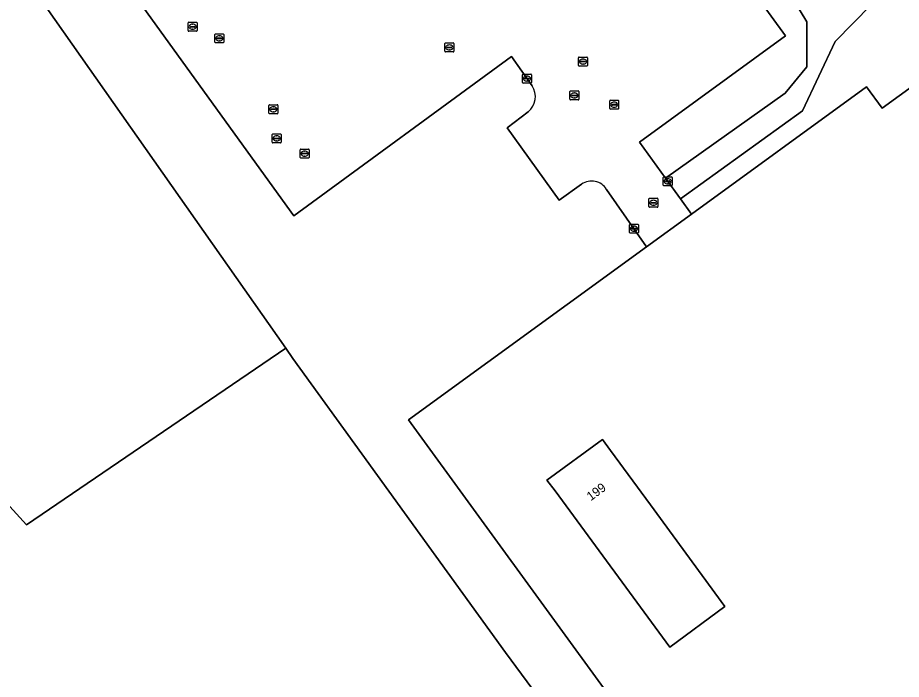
# Model space of a CAD drawing. Extents: x 160203 to 161530, y 379528 to 381797.
# Drawn here: x 160563.5 to 160662.1, y 380137.4 to 380211.2 of the extents above; entities that cross this region are included whole.
import ezdxf

# ---------------------------------------------------------------- set-up
doc = ezdxf.new("R2010")
doc.units = 0
for name, color, linetype in [('IMGEO_Erf', 7, 'Continuous'), ('IMGEO_Grasland_overig', 7, 'Continuous'), ('IMGEO_Kolk', 7, 'Continuous'), ('IMGEO_Loofbos', 7, 'Continuous'), ('IMGEO_Pand', 7, 'Continuous'), ('IMGEO_Pand_nummerreeks', 7, 'Continuous'), ('IMGEO_Parkeervlak_gesloten', 7, 'Continuous'), ('IMGEO_Rioolput', 7, 'Continuous')]:
    doc.layers.add(name, color=color, linetype=linetype)

msp = doc.modelspace()

# ---------------------------------------------------------------- linework, layer by layer
at = {"layer": 'IMGEO_Erf'}
msp.add_lwpolyline([(160832.631, 380116.995), (160854.553, 380138.278), (160818.942, 380187.917), (160814.332, 380194.343), (160832.094, 380207.451), (160830.749, 380209.298), (160801.949, 380188.395), (160801.085, 380189.491), (160829.917, 380210.442), (160817.382, 380227.667), (160800.862, 380223.411), (160795.149, 380250), (160792.697, 380261.409), (160775.626, 380285.117), (160727.25, 380250), (160659.957, 380201.152), (160658.198, 380203.535), (160638.688, 380189.336), (160633.687, 380185.696), (160607.134, 380166.371), (160661.164, 380092.122)], dxfattribs=at)
msp.add_lwpolyline([(160642.426, 380145.565), (160636.258, 380141.042), (160623.467, 380158.449), (160622.573, 380159.665), (160628.767, 380164.187), (160629.66, 380162.97), (160634.108, 380156.906)], close=True, dxfattribs=at)
at = {"layer": 'IMGEO_Grasland_overig'}
for points in [[(160627.796, 380250), (160651.549, 380210.79), (160651.567, 380205.762), (160649.135, 380202.83), (160635.795, 380193.341), (160637.459, 380191.037), (160651.065, 380200.863), (160654.734, 380208.575), (160662.709, 380216.783)], [(160659.204, 380084.561), (160617.929, 380140.449), (160601.914, 380162.597), (160594.235, 380173.217), (160593.422, 380174.377), (160564.504, 380154.675), (160513.808, 380210.429), (160507.442, 380204.215), (160500, 380194.582), (160496.442, 380189.663), (160493.08, 380184.147), (160491.345, 380180.944), (160490.502, 380178.181), (160491.03, 380175.473), (160489.767, 380174.541), (160492.953, 380170.485), (160494.114, 380171.456), (160500, 380164.601), (160528.977, 380132.135)]]:
    msp.add_lwpolyline(points, dxfattribs=at)
msp.add_lwpolyline([(160593.422, 380174.377), (160565.038, 380214.842), (160569.386, 380217.98), (160549.683, 380245.449), (160542.254, 380238.197), (160513.808, 380210.429), (160564.504, 380154.675)], close=True, dxfattribs=at)
at = {"layer": 'IMGEO_Kolk'}
for p, q in [((160585.524, 380208.514), (160585.524, 380209.366)), ((160585.599, 380209.44), (160586.451, 380209.44)), ((160585.783, 380208.934), (160585.783, 380208.946)), ((160586.221, 380208.897), (160585.823, 380208.897)), ((160585.826, 380208.983), (160586.224, 380208.983)), ((160586.035, 380208.66), (160586.01, 380208.66)), ((160586.012, 380209.22), (160586.037, 380209.22)), ((160586.267, 380208.946), (160586.267, 380208.934)), ((160586.525, 380209.366), (160586.525, 380208.514)), ((160586.451, 380208.44), (160585.599, 380208.44)), ((160611.191, 380207.496), (160611.191, 380208.348)), ((160611.266, 380208.422), (160612.118, 380208.422)), ((160611.45, 380207.916), (160611.45, 380207.928)), ((160611.888, 380207.879), (160611.49, 380207.879)), ((160611.493, 380207.965), (160611.891, 380207.965)), ((160611.702, 380207.642), (160611.677, 380207.642)), ((160611.679, 380208.202), (160611.704, 380208.202)), ((160611.934, 380207.928), (160611.934, 380207.916)), ((160612.192, 380208.348), (160612.192, 380207.496)), ((160612.118, 380207.422), (160611.266, 380207.422)), ((160626.082, 380205.924), (160626.082, 380206.776)), ((160626.157, 380206.85), (160627.009, 380206.85)), ((160626.57, 380206.63), (160626.595, 380206.63)), ((160627.083, 380206.776), (160627.083, 380205.924)), ((160627.009, 380205.85), (160626.157, 380205.85)), ((160626.341, 380206.344), (160626.341, 380206.356)), ((160626.779, 380206.307), (160626.381, 380206.307)), ((160626.384, 380206.393), (160626.782, 380206.393)), ((160626.593, 380206.07), (160626.568, 380206.07)), ((160626.825, 380206.356), (160626.825, 380206.344)), ((160619.834, 380204.027), (160619.834, 380204.879)), ((160619.909, 380204.953), (160620.761, 380204.953)), ((160620.322, 380204.733), (160620.347, 380204.733)), ((160620.835, 380204.879), (160620.835, 380204.027)), ((160620.761, 380203.953), (160619.909, 380203.953)), ((160620.093, 380204.447), (160620.093, 380204.459)), ((160620.531, 380204.41), (160620.133, 380204.41)), ((160620.136, 380204.496), (160620.534, 380204.496)), ((160620.345, 380204.173), (160620.32, 380204.173)), ((160620.577, 380204.459), (160620.577, 380204.447)), ((160629.567, 380201.119), (160629.567, 380201.971)), ((160629.642, 380202.045), (160630.494, 380202.045)), ((160630.055, 380201.825), (160630.08, 380201.825)), ((160630.568, 380201.971), (160630.568, 380201.119)), ((160591.552, 380200.604), (160591.552, 380201.456)), ((160591.627, 380201.53), (160592.479, 380201.53)), ((160591.811, 380201.024), (160591.811, 380201.036)), ((160592.249, 380200.987), (160591.851, 380200.987)), ((160591.854, 380201.073), (160592.252, 380201.073)), ((160592.063, 380200.75), (160592.038, 380200.75)), ((160592.04, 380201.31), (160592.065, 380201.31)), ((160592.295, 380201.036), (160592.295, 380201.024)), ((160592.553, 380201.456), (160592.553, 380200.604)), ((160630.494, 380201.045), (160629.642, 380201.045)), ((160629.826, 380201.539), (160629.826, 380201.551)), ((160630.264, 380201.502), (160629.866, 380201.502)), ((160629.869, 380201.588), (160630.267, 380201.588)), ((160630.078, 380201.265), (160630.053, 380201.265)), ((160630.31, 380201.551), (160630.31, 380201.539)), ((160592.479, 380200.53), (160591.627, 380200.53)), ((160595.037, 380195.659), (160595.037, 380196.511)), ((160595.112, 380196.585), (160595.964, 380196.585)), ((160595.296, 380196.079), (160595.296, 380196.091)), ((160595.734, 380196.042), (160595.336, 380196.042)), ((160595.339, 380196.128), (160595.737, 380196.128)), ((160595.548, 380195.805), (160595.523, 380195.805)), ((160595.525, 380196.365), (160595.55, 380196.365)), ((160595.78, 380196.091), (160595.78, 380196.079)), ((160596.038, 380196.511), (160596.038, 380195.659)), ((160595.964, 380195.585), (160595.112, 380195.585)), ((160635.546, 380192.569), (160635.546, 380193.421)), ((160635.621, 380193.495), (160636.473, 380193.495)), ((160635.805, 380192.989), (160635.805, 380193.001)), ((160636.243, 380192.952), (160635.845, 380192.952)), ((160635.848, 380193.038), (160636.246, 380193.038)), ((160636.034, 380193.275), (160636.059, 380193.275)), ((160636.289, 380193.001), (160636.289, 380192.989)), ((160636.547, 380193.421), (160636.547, 380192.569)), ((160636.473, 380192.495), (160635.621, 380192.495)), ((160636.057, 380192.715), (160636.032, 380192.715)), ((160631.775, 380187.288), (160631.775, 380188.14)), ((160631.85, 380188.214), (160632.702, 380188.214)), ((160632.263, 380187.994), (160632.288, 380187.994)), ((160632.776, 380188.14), (160632.776, 380187.288)), ((160632.702, 380187.214), (160631.85, 380187.214)), ((160632.034, 380187.708), (160632.034, 380187.72)), ((160632.472, 380187.671), (160632.074, 380187.671)), ((160632.077, 380187.757), (160632.475, 380187.757)), ((160632.286, 380187.434), (160632.261, 380187.434)), ((160632.518, 380187.72), (160632.518, 380187.708))]:
    msp.add_line(p, q, dxfattribs=at)
for points in [[(160585.524, 380208.514), (160585.524, 380209.366)], [(160585.599, 380209.44), (160586.451, 380209.44)], [(160586.525, 380209.366), (160586.525, 380208.514)], [(160586.451, 380208.44), (160585.599, 380208.44)], [(160611.191, 380207.496), (160611.191, 380208.348)], [(160611.266, 380208.422), (160612.118, 380208.422)], [(160612.192, 380208.348), (160612.192, 380207.496)], [(160612.118, 380207.422), (160611.266, 380207.422)], [(160626.082, 380205.924), (160626.082, 380206.776)], [(160626.157, 380206.85), (160627.009, 380206.85)], [(160627.083, 380206.776), (160627.083, 380205.924)], [(160627.009, 380205.85), (160626.157, 380205.85)], [(160619.834, 380204.027), (160619.834, 380204.879)], [(160619.909, 380204.953), (160620.761, 380204.953)], [(160620.835, 380204.879), (160620.835, 380204.027)], [(160620.761, 380203.953), (160619.909, 380203.953)], [(160629.567, 380201.119), (160629.567, 380201.971)], [(160629.642, 380202.045), (160630.494, 380202.045)], [(160630.568, 380201.971), (160630.568, 380201.119)], [(160591.552, 380200.604), (160591.552, 380201.456)], [(160591.627, 380201.53), (160592.479, 380201.53)], [(160592.553, 380201.456), (160592.553, 380200.604)], [(160630.494, 380201.045), (160629.642, 380201.045)], [(160592.479, 380200.53), (160591.627, 380200.53)], [(160595.037, 380195.659), (160595.037, 380196.511)], [(160595.112, 380196.585), (160595.964, 380196.585)], [(160596.038, 380196.511), (160596.038, 380195.659)], [(160595.964, 380195.585), (160595.112, 380195.585)], [(160635.546, 380192.569), (160635.546, 380193.421)], [(160635.621, 380193.495), (160636.473, 380193.495)], [(160636.547, 380193.421), (160636.547, 380192.569)], [(160636.473, 380192.495), (160635.621, 380192.495)], [(160631.775, 380187.288), (160631.775, 380188.14)], [(160631.85, 380188.214), (160632.702, 380188.214)], [(160632.776, 380188.14), (160632.776, 380187.288)], [(160632.702, 380187.214), (160631.85, 380187.214)]]:
    msp.add_lwpolyline(points, dxfattribs=at)
for centre, radius, start, end in [((160585.601, 380209.364), 0.0765, 91.55205, 178.44795), ((160585.601, 380209.364), 0.0765, 91.55205, 178.44795), ((160585.823, 380208.943), 0.0403, 85.87752, 175.75265), ((160585.82, 380208.933), 0.0366, 178.93798, 274.71019), ((160586.224, 380208.94), 0.043, 264.86636, 352.45326), ((160586.228, 380208.945), 0.0386, 1.73085, 96.63898), ((160586.449, 380209.364), 0.0765, 1.55205, 88.44795), ((160586.449, 380209.364), 0.0765, 1.55205, 88.44795), ((160585.601, 380208.516), 0.0765, 181.55205, 268.44795), ((160585.601, 380208.516), 0.0765, 181.55205, 268.44795), ((160586.449, 380208.516), 0.0765, 271.55205, 358.44795), ((160586.449, 380208.516), 0.0765, 271.55205, 358.44795), ((160611.268, 380208.346), 0.0765, 91.55205, 178.44795), ((160611.268, 380208.346), 0.0765, 91.55205, 178.44795), ((160611.49, 380207.925), 0.0403, 85.87752, 175.75265), ((160611.487, 380207.915), 0.0366, 178.93798, 274.71019), ((160611.891, 380207.922), 0.043, 264.86636, 352.45326), ((160611.895, 380207.927), 0.0386, 1.73085, 96.63898), ((160612.116, 380208.346), 0.0765, 1.55205, 88.44795), ((160612.116, 380208.346), 0.0765, 1.55205, 88.44795), ((160611.268, 380207.498), 0.0765, 181.55205, 268.44795), ((160611.268, 380207.498), 0.0765, 181.55205, 268.44795), ((160612.116, 380207.498), 0.0765, 271.55205, 358.44795), ((160612.116, 380207.498), 0.0765, 271.55205, 358.44795), ((160626.159, 380206.774), 0.0765, 91.55205, 178.44795), ((160626.159, 380206.774), 0.0765, 91.55205, 178.44795), ((160627.007, 380206.774), 0.0765, 1.55205, 88.44795), ((160627.007, 380206.774), 0.0765, 1.55205, 88.44795), ((160626.159, 380205.926), 0.0765, 181.55205, 268.44795), ((160626.159, 380205.926), 0.0765, 181.55205, 268.44795), ((160626.381, 380206.353), 0.0403, 85.87752, 175.75265), ((160626.378, 380206.343), 0.0366, 178.93798, 274.71019), ((160626.782, 380206.35), 0.043, 264.86636, 352.45326), ((160626.786, 380206.355), 0.0386, 1.73085, 96.63898), ((160627.007, 380205.926), 0.0765, 271.55205, 358.44795), ((160627.007, 380205.926), 0.0765, 271.55205, 358.44795), ((160619.911, 380204.877), 0.0765, 91.55205, 178.44795), ((160619.911, 380204.877), 0.0765, 91.55205, 178.44795), ((160620.759, 380204.877), 0.0765, 1.55205, 88.44795), ((160620.759, 380204.877), 0.0765, 1.55205, 88.44795), ((160619.911, 380204.029), 0.0765, 181.55205, 268.44795), ((160619.911, 380204.029), 0.0765, 181.55205, 268.44795), ((160620.133, 380204.456), 0.0403, 85.87752, 175.75265), ((160620.13, 380204.446), 0.0366, 178.93798, 274.71019), ((160620.534, 380204.453), 0.043, 264.86636, 352.45326), ((160620.538, 380204.458), 0.0386, 1.73085, 96.63898), ((160620.759, 380204.029), 0.0765, 271.55205, 358.44795), ((160620.759, 380204.029), 0.0765, 271.55205, 358.44795), ((160629.644, 380201.969), 0.0765, 91.55205, 178.44795), ((160629.644, 380201.969), 0.0765, 91.55205, 178.44795), ((160630.492, 380201.969), 0.0765, 1.55205, 88.44795), ((160630.492, 380201.969), 0.0765, 1.55205, 88.44795), ((160591.629, 380201.454), 0.0765, 91.55205, 178.44795), ((160591.629, 380201.454), 0.0765, 91.55205, 178.44795), ((160591.851, 380201.033), 0.0403, 85.87752, 175.75265), ((160591.848, 380201.023), 0.0366, 178.93798, 274.71019), ((160592.252, 380201.03), 0.043, 264.86636, 352.45326), ((160592.256, 380201.035), 0.0386, 1.73085, 96.63898), ((160592.477, 380201.454), 0.0765, 1.55205, 88.44795), ((160592.477, 380201.454), 0.0765, 1.55205, 88.44795), ((160629.644, 380201.121), 0.0765, 181.55205, 268.44795), ((160629.644, 380201.121), 0.0765, 181.55205, 268.44795), ((160629.866, 380201.548), 0.0403, 85.87752, 175.75265), ((160629.863, 380201.538), 0.0366, 178.93798, 274.71019), ((160630.267, 380201.545), 0.043, 264.86636, 352.45326), ((160630.271, 380201.55), 0.0386, 1.73085, 96.63898), ((160630.492, 380201.121), 0.0765, 271.55205, 358.44795), ((160630.492, 380201.121), 0.0765, 271.55205, 358.44795), ((160591.629, 380200.606), 0.0765, 181.55205, 268.44795), ((160591.629, 380200.606), 0.0765, 181.55205, 268.44795), ((160592.477, 380200.606), 0.0765, 271.55205, 358.44795), ((160592.477, 380200.606), 0.0765, 271.55205, 358.44795), ((160595.114, 380196.509), 0.0765, 91.55205, 178.44795), ((160595.114, 380196.509), 0.0765, 91.55205, 178.44795), ((160595.336, 380196.088), 0.0403, 85.87752, 175.75265), ((160595.333, 380196.078), 0.0366, 178.93798, 274.71019), ((160595.737, 380196.085), 0.043, 264.86636, 352.45326), ((160595.741, 380196.09), 0.0386, 1.73085, 96.63898), ((160595.962, 380196.509), 0.0765, 1.55205, 88.44795), ((160595.962, 380196.509), 0.0765, 1.55205, 88.44795), ((160595.114, 380195.661), 0.0765, 181.55205, 268.44795), ((160595.114, 380195.661), 0.0765, 181.55205, 268.44795), ((160595.962, 380195.661), 0.0765, 271.55205, 358.44795), ((160595.962, 380195.661), 0.0765, 271.55205, 358.44795), ((160635.623, 380193.419), 0.0765, 91.55205, 178.44795), ((160635.623, 380193.419), 0.0765, 91.55205, 178.44795), ((160635.845, 380192.998), 0.0403, 85.87752, 175.75265), ((160635.842, 380192.988), 0.0366, 178.93798, 274.71019), ((160636.246, 380192.995), 0.043, 264.86636, 352.45326), ((160636.25, 380193), 0.0386, 1.73085, 96.63898), ((160636.471, 380193.419), 0.0765, 1.55205, 88.44795), ((160636.471, 380193.419), 0.0765, 1.55205, 88.44795), ((160635.623, 380192.571), 0.0765, 181.55205, 268.44795), ((160635.623, 380192.571), 0.0765, 181.55205, 268.44795), ((160636.471, 380192.571), 0.0765, 271.55205, 358.44795), ((160636.471, 380192.571), 0.0765, 271.55205, 358.44795), ((160631.852, 380188.138), 0.0765, 91.55205, 178.44795), ((160631.852, 380188.138), 0.0765, 91.55205, 178.44795), ((160632.7, 380188.138), 0.0765, 1.55205, 88.44795), ((160632.7, 380188.138), 0.0765, 1.55205, 88.44795), ((160631.852, 380187.29), 0.0765, 181.55205, 268.44795), ((160631.852, 380187.29), 0.0765, 181.55205, 268.44795), ((160632.074, 380187.717), 0.0403, 85.87752, 175.75265), ((160632.071, 380187.707), 0.0366, 178.93798, 274.71019), ((160632.475, 380187.714), 0.043, 264.86636, 352.45326), ((160632.479, 380187.719), 0.0386, 1.73085, 96.63898), ((160632.7, 380187.29), 0.0765, 271.55205, 358.44795), ((160632.7, 380187.29), 0.0765, 271.55205, 358.44795)]:
    msp.add_arc(centre, radius, start, end, dxfattribs=at)
for centre, major_axis, ratio, start_param, end_param in [((160586.011, 380208.94), (-0.387, 0.002), 0.722429, 4.712389, 7.853982), ((160586.036, 380208.94), (-0.39, 0.002), 0.717154, 1.570796, 4.712389), ((160611.678, 380207.922), (-0.387, 0.002), 0.722429, 4.712389, 7.853982), ((160611.703, 380207.922), (-0.39, 0.002), 0.717154, 1.570796, 4.712389), ((160626.569, 380206.35), (-0.387, 0.002), 0.722429, 4.712389, 7.853982), ((160626.594, 380206.35), (-0.39, 0.002), 0.717154, 1.570796, 4.712389), ((160620.321, 380204.453), (-0.387, 0.002), 0.722429, 4.712389, 7.853982), ((160620.346, 380204.453), (-0.39, 0.002), 0.717154, 1.570796, 4.712389), ((160630.054, 380201.545), (-0.387, 0.002), 0.722429, 4.712389, 7.853982), ((160630.079, 380201.545), (-0.39, 0.002), 0.717154, 1.570796, 4.712389), ((160592.039, 380201.03), (-0.387, 0.002), 0.722429, 4.712389, 7.853982), ((160592.064, 380201.03), (-0.39, 0.002), 0.717154, 1.570796, 4.712389), ((160595.524, 380196.085), (-0.387, 0.002), 0.722429, 4.712389, 7.853982), ((160595.549, 380196.085), (-0.39, 0.002), 0.717154, 1.570796, 4.712389), ((160636.033, 380192.995), (-0.387, 0.002), 0.722429, 4.712389, 7.853982), ((160636.058, 380192.995), (-0.39, 0.002), 0.717154, 1.570796, 4.712389), ((160632.262, 380187.714), (-0.387, 0.002), 0.722429, 4.712389, 7.853982), ((160632.287, 380187.714), (-0.39, 0.002), 0.717154, 1.570796, 4.712389)]:
    msp.add_ellipse(centre, major_axis=major_axis, ratio=ratio, start_param=start_param, end_param=end_param, dxfattribs=at)
at = {"layer": 'IMGEO_Loofbos'}
for points in [[(160620.919, 380203.629), (160618.605, 380206.899), (160594.333, 380189.136), (160575.672, 380215.009), (160599.849, 380232.562), (160587.202, 380249.921), (160573.362, 380269.257), (160570.804, 380266.005), (160582.632, 380250), (160593.458, 380235.35), (160569.386, 380217.98), (160565.038, 380214.842), (160593.422, 380174.377), (160594.235, 380173.217), (160601.914, 380162.597), (160617.929, 380140.449), (160659.204, 380084.561)], [(160611.738, 380226.54), (160614.05, 380223.39), (160630.278, 380235.161), (160649.168, 380209.228), (160632.901, 380197.347), (160635.795, 380193.341), (160649.135, 380202.83), (160651.567, 380205.762), (160651.549, 380210.79), (160627.796, 380250)], [(160662.709, 380216.783), (160654.734, 380208.575), (160651.065, 380200.863), (160637.459, 380191.037), (160638.688, 380189.336), (160658.198, 380203.535), (160659.957, 380201.152), (160727.25, 380250)], [(160626.431, 380192.662), (160623.939, 380190.882), (160618.119, 380198.948), (160620.47, 380200.757)], [(160661.164, 380092.122), (160607.134, 380166.371), (160633.687, 380185.696), (160629.224, 380192.083)]]:
    msp.add_lwpolyline(points, dxfattribs=at)
for centre, radius, start, end in [((160619.131, 380202.437), 2.149, 308.54528, 33.68366), ((160627.56, 380191.08), 1.943, 31.06259, 125.51391)]:
    msp.add_arc(centre, radius, start, end, dxfattribs=at)
at = {"layer": 'IMGEO_Pand'}
msp.add_lwpolyline([(160634.108, 380156.906), (160629.66, 380162.97), (160628.767, 380164.187), (160622.573, 380159.665), (160623.467, 380158.449), (160636.258, 380141.042), (160642.426, 380145.565)], close=True, dxfattribs=at)
at = {"layer": 'IMGEO_Parkeervlak_gesloten'}
for points in [[(160612.197, 380229.361), (160614.569, 380231.08), (160608.709, 380238.901), (160605.929, 380236.925), (160599.849, 380232.562), (160575.672, 380215.009), (160594.333, 380189.136), (160618.605, 380206.899), (160620.919, 380203.629)], [(160629.224, 380192.083), (160633.687, 380185.696), (160638.688, 380189.336), (160637.459, 380191.037), (160635.795, 380193.341), (160632.901, 380197.347), (160649.168, 380209.228), (160630.278, 380235.161)], [(160620.47, 380200.757), (160618.119, 380198.948), (160623.939, 380190.882), (160626.431, 380192.662)]]:
    msp.add_lwpolyline(points, dxfattribs=at)
for centre, radius, start, end in [((160619.131, 380202.437), 2.149, 308.54528, 33.68366), ((160627.56, 380191.08), 1.943, 31.06259, 125.51391)]:
    msp.add_arc(centre, radius, start, end, dxfattribs=at)
at = {"layer": 'IMGEO_Rioolput'}
for p, q in [((160582.537, 380209.81), (160582.537, 380210.662)), ((160582.612, 380210.736), (160583.464, 380210.736)), ((160583.025, 380210.516), (160583.05, 380210.516)), ((160583.538, 380210.662), (160583.538, 380209.81)), ((160583.464, 380209.736), (160582.612, 380209.736)), ((160582.796, 380210.23), (160582.796, 380210.242)), ((160583.234, 380210.193), (160582.836, 380210.193)), ((160582.839, 380210.279), (160583.237, 380210.279)), ((160583.048, 380209.956), (160583.023, 380209.956)), ((160583.28, 380210.242), (160583.28, 380210.23)), ((160625.129, 380202.142), (160625.129, 380202.994)), ((160625.204, 380203.068), (160626.056, 380203.068)), ((160625.431, 380202.611), (160625.829, 380202.611)), ((160625.617, 380202.848), (160625.642, 380202.848)), ((160626.13, 380202.994), (160626.13, 380202.142)), ((160626.056, 380202.068), (160625.204, 380202.068)), ((160625.388, 380202.562), (160625.388, 380202.574)), ((160625.826, 380202.525), (160625.428, 380202.525)), ((160625.64, 380202.288), (160625.615, 380202.288)), ((160625.872, 380202.574), (160625.872, 380202.562)), ((160591.919, 380197.352), (160591.919, 380198.204)), ((160591.994, 380198.278), (160592.846, 380198.278)), ((160592.178, 380197.772), (160592.178, 380197.784)), ((160592.616, 380197.735), (160592.218, 380197.735)), ((160592.221, 380197.821), (160592.619, 380197.821)), ((160592.407, 380198.058), (160592.432, 380198.058)), ((160592.662, 380197.784), (160592.662, 380197.772)), ((160592.92, 380198.204), (160592.92, 380197.352)), ((160592.846, 380197.278), (160591.994, 380197.278)), ((160592.43, 380197.498), (160592.405, 380197.498)), ((160633.949, 380190.174), (160633.949, 380191.026)), ((160634.024, 380191.1), (160634.876, 380191.1)), ((160634.437, 380190.88), (160634.462, 380190.88)), ((160634.95, 380191.026), (160634.95, 380190.174)), ((160634.876, 380190.1), (160634.024, 380190.1)), ((160634.208, 380190.594), (160634.208, 380190.606)), ((160634.646, 380190.557), (160634.248, 380190.557)), ((160634.251, 380190.643), (160634.649, 380190.643)), ((160634.46, 380190.32), (160634.435, 380190.32)), ((160634.692, 380190.606), (160634.692, 380190.594))]:
    msp.add_line(p, q, dxfattribs=at)
for points in [[(160582.537, 380209.81), (160582.537, 380210.662)], [(160582.612, 380210.736), (160583.464, 380210.736)], [(160583.538, 380210.662), (160583.538, 380209.81)], [(160583.464, 380209.736), (160582.612, 380209.736)], [(160625.129, 380202.142), (160625.129, 380202.994)], [(160625.204, 380203.068), (160626.056, 380203.068)], [(160626.13, 380202.994), (160626.13, 380202.142)], [(160626.056, 380202.068), (160625.204, 380202.068)], [(160591.919, 380197.352), (160591.919, 380198.204)], [(160591.994, 380198.278), (160592.846, 380198.278)], [(160592.92, 380198.204), (160592.92, 380197.352)], [(160592.846, 380197.278), (160591.994, 380197.278)], [(160633.949, 380190.174), (160633.949, 380191.026)], [(160634.024, 380191.1), (160634.876, 380191.1)], [(160634.95, 380191.026), (160634.95, 380190.174)], [(160634.876, 380190.1), (160634.024, 380190.1)]]:
    msp.add_lwpolyline(points, dxfattribs=at)
for centre, radius, start, end in [((160582.614, 380210.66), 0.0765, 91.55205, 178.44795), ((160582.614, 380210.66), 0.0765, 91.55205, 178.44795), ((160583.462, 380210.66), 0.0765, 1.55205, 88.44795), ((160583.462, 380210.66), 0.0765, 1.55205, 88.44795), ((160582.614, 380209.812), 0.0765, 181.55205, 268.44795), ((160582.614, 380209.812), 0.0765, 181.55205, 268.44795), ((160582.836, 380210.239), 0.0403, 85.87752, 175.75265), ((160582.833, 380210.229), 0.0366, 178.93798, 274.71019), ((160583.237, 380210.236), 0.043, 264.86636, 352.45326), ((160583.241, 380210.241), 0.0386, 1.73085, 96.63898), ((160583.462, 380209.812), 0.0765, 271.55205, 358.44795), ((160583.462, 380209.812), 0.0765, 271.55205, 358.44795), ((160625.206, 380202.992), 0.0765, 91.55205, 178.44795), ((160625.206, 380202.992), 0.0765, 91.55205, 178.44795), ((160625.428, 380202.571), 0.0403, 85.87752, 175.75265), ((160625.833, 380202.573), 0.0386, 1.73085, 96.63898), ((160626.054, 380202.992), 0.0765, 1.55205, 88.44795), ((160626.054, 380202.992), 0.0765, 1.55205, 88.44795), ((160625.206, 380202.144), 0.0765, 181.55205, 268.44795), ((160625.206, 380202.144), 0.0765, 181.55205, 268.44795), ((160625.425, 380202.561), 0.0366, 178.93798, 274.71019), ((160625.829, 380202.568), 0.043, 264.86636, 352.45326), ((160626.054, 380202.144), 0.0765, 271.55205, 358.44795), ((160626.054, 380202.144), 0.0765, 271.55205, 358.44795), ((160591.996, 380198.202), 0.0765, 91.55205, 178.44795), ((160591.996, 380198.202), 0.0765, 91.55205, 178.44795), ((160592.218, 380197.781), 0.0403, 85.87752, 175.75265), ((160592.215, 380197.771), 0.0366, 178.93798, 274.71019), ((160592.619, 380197.778), 0.043, 264.86636, 352.45326), ((160592.623, 380197.783), 0.0386, 1.73085, 96.63898), ((160592.844, 380198.202), 0.0765, 1.55205, 88.44795), ((160592.844, 380198.202), 0.0765, 1.55205, 88.44795), ((160591.996, 380197.354), 0.0765, 181.55205, 268.44795), ((160591.996, 380197.354), 0.0765, 181.55205, 268.44795), ((160592.844, 380197.354), 0.0765, 271.55205, 358.44795), ((160592.844, 380197.354), 0.0765, 271.55205, 358.44795), ((160634.026, 380191.024), 0.0765, 91.55205, 178.44795), ((160634.026, 380191.024), 0.0765, 91.55205, 178.44795), ((160634.874, 380191.024), 0.0765, 1.55205, 88.44795), ((160634.874, 380191.024), 0.0765, 1.55205, 88.44795), ((160634.026, 380190.176), 0.0765, 181.55205, 268.44795), ((160634.026, 380190.176), 0.0765, 181.55205, 268.44795), ((160634.248, 380190.603), 0.0403, 85.87752, 175.75265), ((160634.245, 380190.593), 0.0366, 178.93798, 274.71019), ((160634.649, 380190.6), 0.043, 264.86636, 352.45326), ((160634.653, 380190.605), 0.0386, 1.73085, 96.63898), ((160634.874, 380190.176), 0.0765, 271.55205, 358.44795), ((160634.874, 380190.176), 0.0765, 271.55205, 358.44795)]:
    msp.add_arc(centre, radius, start, end, dxfattribs=at)
for centre, major_axis, ratio, start_param, end_param in [((160583.024, 380210.236), (-0.387, 0.002), 0.722429, 4.712389, 7.853982), ((160583.049, 380210.236), (-0.39, 0.002), 0.717154, 1.570796, 4.712389), ((160625.616, 380202.568), (-0.387, 0.002), 0.722429, 4.712389, 7.853982), ((160625.641, 380202.568), (-0.39, 0.002), 0.717154, 1.570796, 4.712389), ((160592.406, 380197.778), (-0.387, 0.002), 0.722429, 4.712389, 7.853982), ((160592.431, 380197.778), (-0.39, 0.002), 0.717154, 1.570796, 4.712389), ((160634.436, 380190.6), (-0.387, 0.002), 0.722429, 4.712389, 7.853982), ((160634.461, 380190.6), (-0.39, 0.002), 0.717154, 1.570796, 4.712389)]:
    msp.add_ellipse(centre, major_axis=major_axis, ratio=ratio, start_param=start_param, end_param=end_param, dxfattribs=at)

# ---------------------------------------------------------------- texts
at = {"layer": 'IMGEO_Pand_nummerreeks'}
msp.add_text('199', height=1, rotation=36.13072, dxfattribs=at).set_placement((160627.457, 380157.301))

doc.saveas('drawing.dxf')
